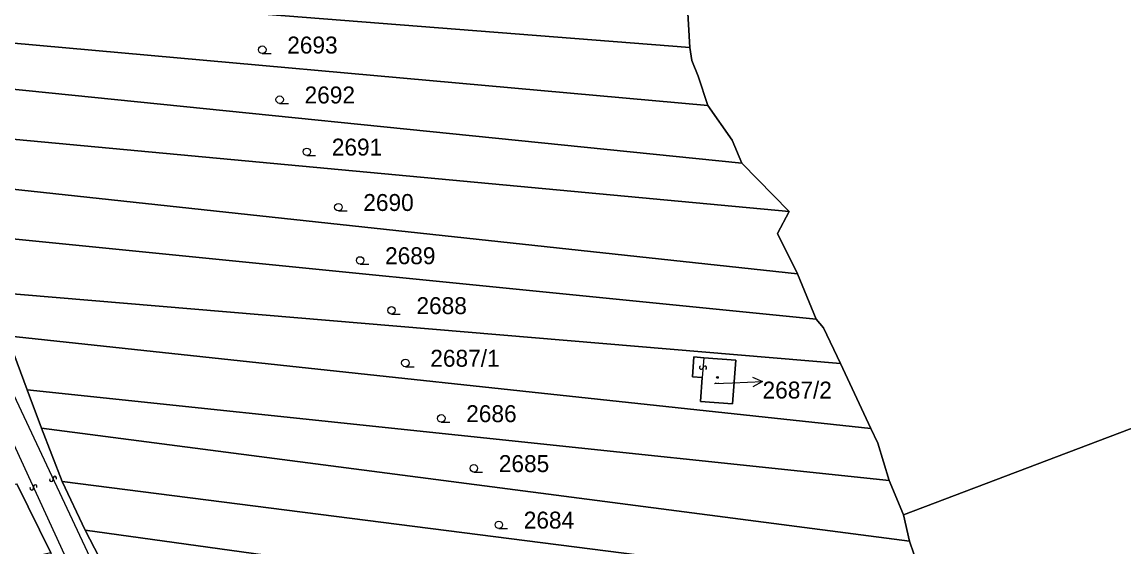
# Model space of a CAD drawing. Extents: x -596024 to -594475, y -1163820 to -1161957.
# Drawn here: x -595677.9 to -595567.4, y -1163214.5 to -1163161.8 of the extents above; entities that cross this region are included whole.
import ezdxf

# ---------------------------------------------------------------- set-up
doc = ezdxf.new("R2010")
doc.units = 0
for name, color, linetype in [('Level 1', 7, 'Continuous'), ('Level 13', 7, 'Continuous'), ('Level 3', 7, 'Continuous'), ('Level 4', 7, 'Continuous'), ('Level 5', 7, 'Continuous'), ('Level 57', 7, 'Continuous'), ('Level 60', 7, 'Continuous')]:
    doc.layers.add(name, color=color, linetype=linetype)

msp = doc.modelspace()

# ---------------------------------------------------------------- linework, layer by layer
at = {"layer": 'Level 1'}
for points in [[(-595437.23, -1163153.46), (-595589.56, -1163211.26)], [(-595692.17, -1163157.96), (-595610.98, -1163164.36)], [(-595610.98, -1163164.36), (-595611.27, -1163159.13)], [(-595690.34, -1163162.9), (-595609.16, -1163170.18)], [(-595609.16, -1163170.18), (-595610.15, -1163167.24), (-595610.78, -1163165.65), (-595610.98, -1163164.36)], [(-595605.75, -1163175.97), (-595688.79, -1163167.54)], [(-595605.75, -1163175.97), (-595606.73, -1163173.64), (-595609.16, -1163170.18)], [(-595686.83, -1163172.82), (-595601.01, -1163180.8)], [(-595601.01, -1163180.8), (-595605.75, -1163175.97)], [(-595600.19, -1163187.08), (-595685.12, -1163177.89)], [(-595600.19, -1163187.08), (-595602.19, -1163183.01), (-595601.01, -1163180.8)], [(-595683.29, -1163183.13), (-595598.29, -1163191.63)], [(-595598.29, -1163191.63), (-595600.19, -1163187.08)], [(-595595.87, -1163196.08), (-595681.3, -1163188.87)], [(-595595.87, -1163196.08), (-595597.57, -1163192.49), (-595598.29, -1163191.63)], [(-595677.43, -1163198.7), (-595679.42, -1163193.3)], [(-595679.42, -1163193.3), (-595592.81, -1163202.58)], [(-595609.56, -1163195.48), (-595610.56, -1163195.4), (-595610.71, -1163197.4), (-595609.72, -1163197.48)], [(-595609.56, -1163195.48), (-595606.37, -1163195.73), (-595606.71, -1163200.12), (-595609.9, -1163199.87), (-595609.72, -1163197.48)], [(-595592.81, -1163202.58), (-595595.87, -1163196.08)], [(-595675.99, -1163202.55), (-595677.43, -1163198.7)], [(-595590.97, -1163207.82), (-595677.43, -1163198.7)], [(-595673.91, -1163207.9), (-595675.99, -1163202.55)], [(-595675.99, -1163202.55), (-595588.93, -1163213.88)], [(-595590.97, -1163207.82), (-595592.11, -1163204.07), (-595592.81, -1163202.58)], [(-595675.06, -1163215.07), (-595678.46, -1163208.15)], [(-595671.63, -1163212.8), (-595673.91, -1163207.9)], [(-595587.19, -1163218.99), (-595673.91, -1163207.9)], [(-595589.56, -1163211.26), (-595590.97, -1163207.82)], [(-595588.93, -1163213.88), (-595589.56, -1163211.26)], [(-595669.24, -1163217.36), (-595671.63, -1163212.8)], [(-595671.63, -1163212.8), (-595585.26, -1163224.77)], [(-595587.19, -1163218.99), (-595588.93, -1163213.88)]]:
    msp.add_lwpolyline(points, dxfattribs=at)
at = {"layer": 'Level 13'}
for centre, start, end in [((-595609.82, -1163196.46), 122.5844, 355.1744), ((-595609.46, -1163196.5), 302.7988, 174.8968), ((-595676.63, -1163208.42), 331.8399, 204.4299), ((-595675, -1163207.73), 152.5463, 24.6443), ((-595674.66, -1163207.57), 332.3318, 204.9218), ((-595676.97, -1163208.58), 152.0544, 24.1523)]:
    msp.add_arc(centre, 0.184, start, end, dxfattribs=at)
at = {"layer": 'Level 3'}
for points in [[(-595589.06, -1163369.57), (-595605.82, -1163354.55), (-595624.37, -1163318.41), (-595627.64, -1163311.14), (-595640.13, -1163280.53), (-595658.11, -1163241.42), (-595667.31, -1163223.65), (-595682.35, -1163191.65), (-595714.56, -1163109.73), (-595719.08, -1163103.49)], [(-595570.47, -1163380.31), (-595590.93, -1163371.07), (-595607.77, -1163356.11), (-595622.34, -1163330.36), (-595626.4, -1163320.04), (-595629.2, -1163312.39), (-595641.66, -1163281.25), (-595659.92, -1163242.26), (-595669.39, -1163224.63), (-595684.22, -1163192.36), (-595704.51, -1163138.34), (-595716.42, -1163110.71), (-595720.5, -1163104.83)], [(-595609.56, -1163195.48), (-595609.72, -1163197.48)]]:
    msp.add_lwpolyline(points, dxfattribs=at)
at = {"layer": 'Level 5'}
for p, q in [((-595653.85, -1163164.96), (-595652.97, -1163164.96)), ((-595652.11, -1163169.97), (-595651.23, -1163169.97)), ((-595649.38, -1163175.2), (-595648.51, -1163175.2)), ((-595646.22, -1163180.76), (-595645.34, -1163180.76)), ((-595644.04, -1163186.1), (-595643.17, -1163186.1)), ((-595640.89, -1163191.11), (-595640.02, -1163191.11)), ((-595639.5, -1163196.39), (-595638.62, -1163196.39)), ((-595635.9, -1163201.95), (-595635.03, -1163201.95)), ((-595632.63, -1163206.96), (-595631.76, -1163206.96)), ((-595630.13, -1163212.63), (-595629.26, -1163212.63))]:
    msp.add_line(p, q, dxfattribs=at)
for centre, radius in [((-595653.85, -1163164.58), 0.375), ((-595652.11, -1163169.59), 0.375), ((-595649.38, -1163174.82), 0.375), ((-595646.22, -1163180.38), 0.375), ((-595644.04, -1163185.72), 0.375), ((-595640.89, -1163190.73), 0.375), ((-595639.5, -1163196.01), 0.375), ((-595608.21, -1163197.46), 0.09), ((-595608.21, -1163197.46), 0.0521), ((-595635.9, -1163201.57), 0.375), ((-595632.63, -1163206.58), 0.375), ((-595630.13, -1163212.25), 0.375)]:
    msp.add_circle(centre, radius, dxfattribs=at)
at = {"layer": 'Level 57'}
for p, q in [((-595608.5, -1163198.06), (-595606.68, -1163197.99)), ((-595606.68, -1163197.99), (-595603.68, -1163197.88))]:
    msp.add_line(p, q, dxfattribs=at)
msp.add_lwpolyline([(-595604.7, -1163197.42), (-595603.68, -1163197.88), (-595604.66, -1163198.42)], dxfattribs=at)
at = {"layer": 'Level 60'}
for points in [[(-595611.27, -1163159.13), (-595610.98, -1163164.36), (-595692.17, -1163157.96), (-595694.77, -1163152.59)], [(-595437.23, -1163153.46), (-595429.2, -1163170.59), (-595427.11, -1163175.6), (-595408.9, -1163214.29), (-595354.36, -1163375.3), (-595383.32, -1163386.51), (-595411.35, -1163396.88), (-595424.19, -1163373.84), (-595488.9, -1163237.6), (-595566.98, -1163268.91), (-595567.89, -1163267.83), (-595572.12, -1163262.14), (-595574.34, -1163257.62), (-595576.23, -1163252.16), (-595576.47, -1163250.5), (-595577.89, -1163246.83), (-595579.6, -1163241.5), (-595581.35, -1163236.18), (-595582.85, -1163231.46), (-595583.38, -1163230.54), (-595585.26, -1163224.77), (-595587.19, -1163218.99), (-595588.93, -1163213.88), (-595589.56, -1163211.26)], [(-595610.15, -1163167.24), (-595609.16, -1163170.18), (-595690.34, -1163162.9), (-595691.04, -1163160.31), (-595692.17, -1163157.96), (-595610.98, -1163164.36), (-595610.78, -1163165.65)], [(-595606.73, -1163173.64), (-595605.75, -1163175.97), (-595688.79, -1163167.54), (-595690.34, -1163162.9), (-595609.16, -1163170.18)], [(-595605.75, -1163175.97), (-595601.01, -1163180.8), (-595686.83, -1163172.82), (-595688.79, -1163167.54)], [(-595602.19, -1163183.01), (-595600.19, -1163187.08), (-595685.12, -1163177.89), (-595686.83, -1163172.82), (-595601.01, -1163180.8)], [(-595600.19, -1163187.08), (-595598.29, -1163191.63), (-595683.29, -1163183.13), (-595685.12, -1163177.89)], [(-595597.57, -1163192.49), (-595595.87, -1163196.08), (-595681.3, -1163188.87), (-595683.29, -1163183.13), (-595598.29, -1163191.63)], [(-595595.87, -1163196.08), (-595592.81, -1163202.58), (-595679.42, -1163193.3), (-595681.3, -1163188.87)], [(-595592.11, -1163204.07), (-595590.97, -1163207.82), (-595677.43, -1163198.7), (-595679.42, -1163193.3), (-595592.81, -1163202.58)], [(-595609.56, -1163195.48), (-595610.56, -1163195.4), (-595610.71, -1163197.4), (-595609.72, -1163197.48), (-595609.9, -1163199.87), (-595606.71, -1163200.12), (-595606.37, -1163195.73)], [(-595610.56, -1163195.4), (-595609.56, -1163195.48), (-595606.37, -1163195.73), (-595606.71, -1163200.12), (-595609.9, -1163199.87), (-595609.72, -1163197.48), (-595610.71, -1163197.4)], [(-595589.56, -1163211.26), (-595588.93, -1163213.88), (-595675.99, -1163202.55), (-595677.43, -1163198.7), (-595590.97, -1163207.82)], [(-595588.93, -1163213.88), (-595587.19, -1163218.99), (-595673.91, -1163207.9), (-595675.99, -1163202.55)], [(-595828.78, -1163230.26), (-595802.13, -1163230.39), (-595778.15, -1163228.18), (-595776.87, -1163228.06), (-595742.94, -1163222.14), (-595678.46, -1163208.15), (-595675.06, -1163215.07), (-595742.82, -1163230.33), (-595776.16, -1163236.05), (-595801.34, -1163238.84), (-595828.3, -1163237.91), (-595878.95, -1163232.89), (-595915.65, -1163229.59), (-595911, -1163228.8), (-595895.98, -1163224.61), (-595891.99, -1163224.95)], [(-595587.19, -1163218.99), (-595585.26, -1163224.77), (-595671.63, -1163212.8), (-595673.91, -1163207.9)], [(-595585.26, -1163224.77), (-595583.38, -1163230.54), (-595669.24, -1163217.36), (-595671.63, -1163212.8)]]:
    msp.add_lwpolyline(points, close=True, dxfattribs=at)
for points in [[(-595437.23, -1163153.46), (-595589.56, -1163211.26), (-595590.97, -1163207.82), (-595592.11, -1163204.07), (-595592.81, -1163202.58), (-595595.87, -1163196.08), (-595597.57, -1163192.49), (-595598.29, -1163191.63), (-595600.19, -1163187.08), (-595602.19, -1163183.01), (-595601.01, -1163180.8), (-595605.75, -1163175.97), (-595606.73, -1163173.64), (-595609.16, -1163170.18), (-595610.15, -1163167.24), (-595610.78, -1163165.65), (-595610.98, -1163164.36), (-595611.27, -1163159.13)], [(-595679.42, -1163193.3), (-595677.43, -1163198.7), (-595675.99, -1163202.55), (-595673.91, -1163207.9), (-595671.63, -1163212.8), (-595669.24, -1163217.36), (-595666.92, -1163222.22), (-595663.83, -1163227.41), (-595661.6, -1163231.72), (-595659.11, -1163236.59), (-595657.13, -1163241.93), (-595654.41, -1163246.96), (-595652, -1163252.4), (-595649.43, -1163257.78), (-595646.85, -1163263.29), (-595645.38, -1163267.56), (-595642.78, -1163273.37), (-595640.46, -1163278.03), (-595638.03, -1163282.43), (-595635.33, -1163287.47), (-595633.52, -1163292.47), (-595631.17, -1163297.72), (-595629.18, -1163302.43), (-595627.73, -1163307.34)], [(-595570.47, -1163380.31), (-595591.53, -1163371.55), (-595608.09, -1163356.36), (-595622.47, -1163331.43), (-595631.99, -1163314.26), (-595634.65, -1163307.58), (-595637.21, -1163300.06), (-595640.41, -1163291.29), (-595643.76, -1163282.23), (-595645.78, -1163276.33), (-595647.23, -1163272.55), (-595649.76, -1163267.23), (-595652.29, -1163261.91), (-595656.6, -1163252.96), (-595658.54, -1163248.02), (-595659.73, -1163244.35), (-595661.36, -1163240.73), (-595665.63, -1163233.08), (-595667.91, -1163228.35), (-595671.73, -1163222.03), (-595675.06, -1163215.07), (-595678.46, -1163208.15)]]:
    msp.add_lwpolyline(points, dxfattribs=at)

# ---------------------------------------------------------------- texts
at = {"layer": 'Level 4'}
for s, height, p in [('2693', 1.7, (-595651.35, -1163164.96)), ('2692', 1.7, (-595649.61, -1163169.97)), ('2691', 1.7, (-595646.88, -1163175.2)), ('2690', 1.7, (-595643.72, -1163180.76)), ('2689', 1.7, (-595641.54, -1163186.1)), ('2688', 1.7, (-595638.39, -1163191.11)), ('2687/1', 1.7, (-595637, -1163196.39)), ('2687/2', 0.1, (-595608.5, -1163198.06)), ('2686', 1.7, (-595633.4, -1163201.95)), ('2685', 1.7, (-595630.13, -1163206.96)), ('2684', 1.7, (-595627.63, -1163212.63))]:
    msp.add_text(s, height=height, dxfattribs=at).set_placement(p)
at = {"layer": 'Level 57'}
msp.add_text('2687/2', height=1.7, dxfattribs=at).set_placement((-595603.68, -1163199.58))

doc.saveas('drawing.dxf')
